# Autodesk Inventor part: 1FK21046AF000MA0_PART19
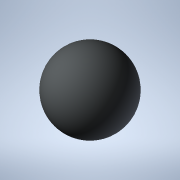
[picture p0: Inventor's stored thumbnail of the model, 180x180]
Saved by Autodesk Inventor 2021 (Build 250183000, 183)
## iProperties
Created: 2025-04
Part Number: 1FK21046AF000MA0_PART19
Material: Generic
Catalog Web Link: www.3dfindit.com
Description: -Servo synchronous motor
Document SubType Name: Modeling
Designer: psAdmin
Mass: 0.137258 g
Surface Area: 1.2868 cm^2
Volume: 0.137258 cm^3
Density: 1 g/cm^3
Appearance: PSOLRGB-212-217-219
Category: PARTsolutions
Title: 1FK21046AF000MA0_PART19
Author: Cadenas PARTsolutions
Comments: Servo synchronous motor
Sending System: PARTsolutions
Preprocessor: ST-DEVELOPER v19.3
PSOL_IDENT_0: {$CADENAS_DATA/23d-libs/siemens_ag/_cat_/1c/1f/1fk21046af000ma0.prj},216 {VTYP=3D},{NB=1FK21046AF000
PSOL_IDENT_1: MA0_PART19},{LINA=1FK21046AF000MA0_PART19},{NN=1FK21046AF000MA0_PART19},{NOPRJ=TRUE},{DATE=19.08.202
PSOL_IDENT_2: 5 14:00:28},{GEOMDATE=30.07.2025 02:02:08},{VERSION=},{LINEID=10},{WBVAR=},{WBNUMERIC=}  {NB=1FK2104
PSOL_IDENT_3: 6AF000MA0_PART19},{LINA=1FK21046AF000MA0_PART19},{KT=DUMMY},{PREVIEW=../../../_pool_/cb/72/p_d211_xx
PSOL_IDENT_4: _00434j.png},{DESCSHORT=SIMOTICS S-1FK2 HD, SINAMICS S210 3AC 400V-480V, 3.2 Nm, 3000 rpm},{DESCLONG=
PSOL_IDENT_5: SIMOTICS S-1FK2 HD servo motor M0=3.2 Nm; PN = 1 kW at nN=3000 rpm (380-480 V); PN = 0.5 kW at nN=15
PSOL_IDENT_6: 00 rpm (200-240 V); degree of protection IP64; cylindrical shaft D19x40mm; absolute encoder 22-bit +
PSOL_IDENT_7: 12-bit multiturn (encoder AM22DQC); with OCC interface; plug size M17, rotatable; SIMOTICS S-1FK2 s
PSOL_IDENT_8: ervomotorfor a wide range of uses in industrial environments. SIMOTICS S‑1FK2 servomotors are compac
PSOL_IDENT_9: t synchronous motors with a high dynamic performance that set themselves apart as a result of their
PSOL_IDENT_10: high power density, degree of protection and overload capability. The motors are available in two va
PSOL_IDENT_11: riants: as High Dynamic variant (highest dynamic performance as a result of the low intrinsic moment
PSOL_IDENT_12: of inertia for applications demanding a high dynamic performance with low moved masses) - and as Co
PSOL_IDENT_13: mpact variant (precise and stable closed-loop control for medium up to large moved masses as a resul
PSOL_IDENT_14: t of a medium intrinsic moment of inertia). SIMOTICSS‑1FK2 servomotors fully exploit their strengths
PSOL_IDENT_15: in a system with the SINAMICSS210 frequency converter and simple connection using the one cable con
PSOL_IDENT_16: nection (OCC). Advantages include the short control and positioning times, fast and precise correcti
PSOL_IDENT_17: on of disturbing quantities as well as stable control with a high dynamic performance. The servo mot
PSOL_IDENT_18: ors can be configured to address a wide range of requirements. For example with and without holding
PSOL_IDENT_19: brake, IP64 or IP65 degree of protection, singleturn or multiturn absolute encoders - to name just a
PSOL_IDENT_20: few. Further, the servomotors are available in different shaft heights extending from 20 to 100. A
PSOL_IDENT_21: shaft sealing ring is available to achieve an IP65 degree of protection and for subsequent mounting
PSOL_IDENT_22: at the motor or as spare part. SIMOTICS - the optimum motor for each and every motion control applic
PSOL_IDENT_23: ation.},{INTNO=195125049666},{SUPPLIERALTNO=1FK2104-6AF00-0MA0},{MANUID=1FK21046AF000MA0},{MANUNAME=
PSOL_IDENT_24: Siemens},{MANUTYPEDESC=Synchronous motor 1FK2-HD 3.2 NM},{AAU732=SIMOTICS},{AAO057=S-1FK2},{AAU734=S
PSOL_IDENT_25: IMOTICS S-1FK2 HD servo motor M0=3.2 Nm; PN = 1 kW at nN=3000 rpm (380-480 V); PN = 0.5 kW at nN=150
PSOL_IDENT_26: 0 rpm (200-240 V); degree of protection IP64; cylindrical shaft D19x40mm; absolute encoder 22-bit +
PSOL_IDENT_27: 12-bit multiturn (encoder AM22DQC); with OCC interface; plug size M17, rotatable;},{AAW338=Synchrono
PSOL_IDENT_28: us motor 1FK2-HD 3.2 NM},{AAO742=SIMOTICS},{AAO663=4042948694374},{NOCUPEROU=1},{PRICEQUANTITY=1},{Q
PSOL_IDENT_29: UANTITYMIN=1},{QUANTITYINT=1},{CTN=85015220},{COO=DE},{AAO676=1FK2104-6AF00-0MA0},{AAO677=Siemens AG
PSOL_IDENT_30: },{ORDERUNIT=C62},{CONTENTUNIT=C62}
NB: 1FK21046AF000MA0_PART19
NT: Servo synchronous motor
NBSYN: $MANUID._PART19
LINA: 1FK21046AF000MA0_PART19
CATALOG: SIEMENS
PREVIEW: ../../../_pool_/cb/72/p_d211_xx_00434j.png
DESCSHORT: SIMOTICS S-1FK2 HD, SINAMICS S210 3AC 400V-480V, 3.2 Nm, 3000 rpm
DESCLONG: SIMOTICS S-1FK2 HD servo motor M0=3.2 Nm; PN = 1 kW at nN=3000 rpm (380-480 V); PN = 0.5 kW at nN=1500 rpm (200-240 V); degree of protection IP64; cylindrical s
INTNO: 195125049666
SUPPLIERALTNO: 1FK2104-6AF00-0MA0
MANUID: 1FK21046AF000MA0
MANUNAME: Siemens
MANUTYPEDESC: Synchronous motor 1FK2-HD 3.2 NM
AAU732: SIMOTICS
AAO057: S-1FK2
AAU734: SIMOTICS S-1FK2 HD servo motor M0=3.2 Nm; PN = 1 kW at nN=3000 rpm (380-480 V); PN = 0.5 kW at nN=1500 rpm (200-240 V); degree of protection IP64; cylindrical s
AAW338: Synchronous motor 1FK2-HD 3.2 NM
AAO742: SIMOTICS
AAO663: 4042948694374.0
NOCUPEROU: 1
PRICEQUANTITY: 1
QUANTITYMIN: 1
QUANTITYINT: 1
CTN: 85015220
COO: DE
ARTICLENO: 1FK21046AF000MA0_PART19
BOMINFO: 1FK21046AF000MA0_PART19
CREATOR: CADENAS GmbH
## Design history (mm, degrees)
feature "2025_04_17_15_39_11_0412"
body "Solid1"
